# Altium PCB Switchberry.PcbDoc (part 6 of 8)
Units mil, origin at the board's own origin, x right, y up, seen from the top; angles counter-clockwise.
Board outline 4500 x 3824.8 mil, 6 copper layers (L01-TOP, L02-GND, L03-SIG, L04-SIG, L05-GND, L06-BOT), stack 49.214 mil thick; 431 components, 322 nets, 1699 pads, 1274 vias.
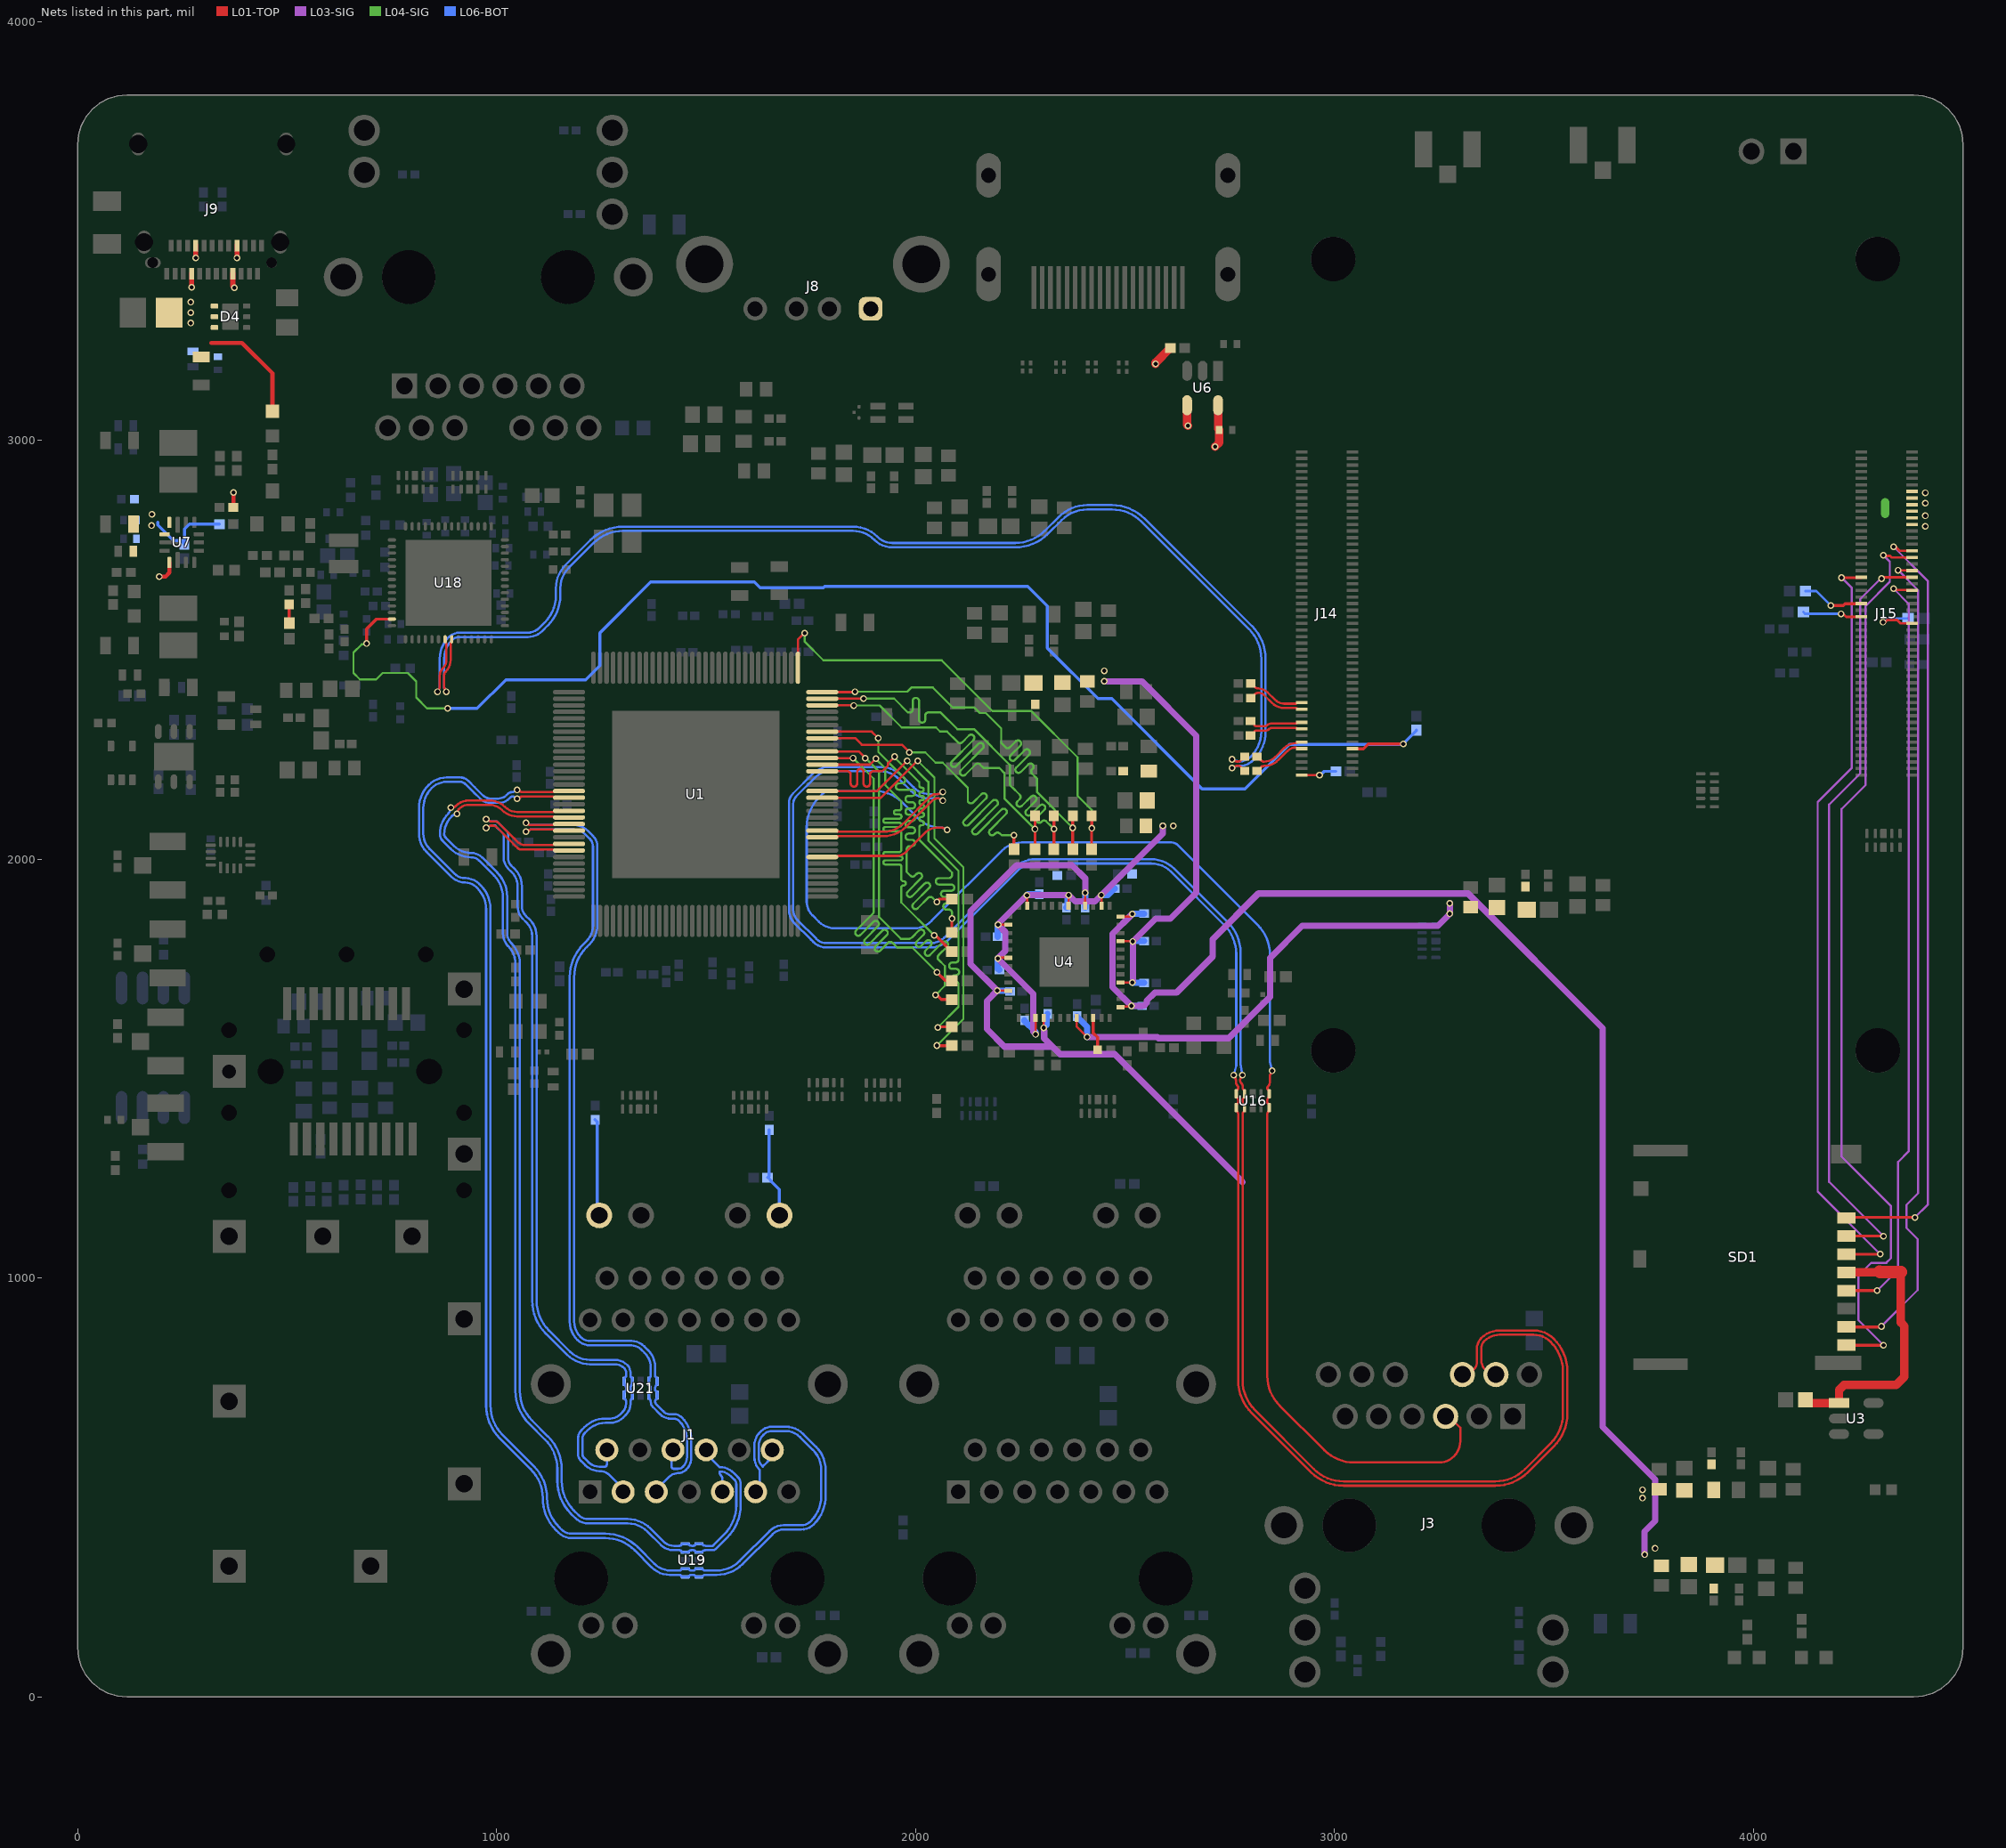
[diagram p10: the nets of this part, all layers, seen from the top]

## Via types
v1: diameter 16, hole 10, L01-TOP to L06-BOT, tented both sides, 1262 vias
v2: diameter 11.81, hole 7.87, L01-TOP to L06-BOT, tented both sides, 4 vias
v3: diameter 19.68, hole 7.87, L01-TOP to L06-BOT, tented both sides, 4 vias
v4: diameter 157.48, hole 110.24, L01-TOP to L06-BOT, tented both sides, 4 vias

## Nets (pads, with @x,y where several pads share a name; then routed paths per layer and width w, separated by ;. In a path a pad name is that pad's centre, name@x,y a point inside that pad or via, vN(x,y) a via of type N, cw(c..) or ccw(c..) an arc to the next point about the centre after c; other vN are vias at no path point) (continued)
P4_TXRXC_P: J3.3 U1.39 U16.1 U16.10 | length 3955.4
  L01-TOP w5.38: U1.39@1777.18,2005.39 1809.86,2005.39 ccw(c1809.86,2009.98) 1813.1,2006.74 cw(c1816.34,2003.5) 1816.34,2008.08 1954.23,2008.08 ccw(c1954.23,2040.73) 1977.32,2017.64 2025.21,2065.54 cw(c2048.75,2042.08) 2048.75,2075.31 2063.06,2075.31 cw(c2063.06,2066.24) 2069.47,2072.66 2070.09,2072.03 ccw(c2075,2076.94) v1(2075,2070) ; v1(2851,1495) cw(c2844.06,1495) 2848.97,1490.1 2848.34,1489.47 ccw(c2854.76,1483.06) 2845.69,1483.06 2845.69,1468.99 cw(c2829.6,1468.99) 2840.98,1457.61 ccw(c2844.78,1453.81) 2839.4,1453.81 ccw(c2844.78,1453.81) 2840.98,1450.01 2842.55,1448.43 2842.81,1448.43 2843.43,1447.81 cw(c2841.92,1446.3) 2844.06,1446.3 U16.1@2844.06,1440 2844.06,1433.7 cw(c2841.92,1433.7) 2843.43,1432.19 2842.81,1431.57 2842.55,1431.57 ccw(c2850.16,1423.96) 2839.4,1423.96 2839.4,1420.94 ccw(c2844.78,1420.94) 2840.98,1417.13 2842.55,1415.56 2842.81,1415.56 cw(c2839.79,1412.55) 2844.06,1412.55 U16.10@2844.06,1407.13 2844.06,1400.82 cw(c2841.92,1400.82) 2843.43,1399.32 2842.81,1398.69 2842.55,1398.69 ccw(c2850.16,1391.09) 2839.4,1391.09 2839.4,767.02 ccw(c2939.4,767.02) 2868.69,696.31 2975.71,589.29 ccw(c3046.42,660) 3046.42,560 3248.79,560 ccw(c3248.79,611.21) 3285,575 ccw(c3249.13,610.87) 3299.86,610.87 3299.86,643.32 3278.96,664.22 ccw(c3265,650.25) J3.3@3265,670
  L06-BOT w5.38: 1903.45,2162.87 1792.39,2162.87 ccw(c1792.39,2144.56) 1779.44,2157.51 1769.29,2147.36 ccw(c1840,2076.65) 1740,2076.65 1740,1899.37 ccw(c1786.76,1899.37) 1753.69,1866.31 1769.16,1850.84 ccw(c1806.49,1888.17) 1806.49,1835.38 1996.42,1835.38 ccw(c1996.42,1894.01) 2037.87,1852.55 2205.98,2020.66 cw(c2253.55,1973.14) 2206.03,2020.71 cw(c2253.55,1973.14) 2253.55,2040.38 2604.05,2040.38 cw(c2604.05,1968.14) 2616.38,2039.32 cw(c2613.58,2023.81) 2624.71,2034.96 2644.51,2015.17 2816.4,1843.28 cw(c2745.69,1772.57) 2845.69,1772.57 2845.69,1519.71 2845.69,1516.94 v1(2851,1495) ; 1903.49,2162.87 cw(c1903.52,2072.77) 1967.25,2136.47 ; 1967.28,2136.43 2004.59,2099.13 ccw(c2062.09,2156.64) 2062.09,2075.31 2062.18,2075.31 cw(c2062.18,2064.12) 2070.09,2072.03 ccw(c2075,2076.94) v1(2075,2070)
P4_TXRXD_N: J3.9 U1.43 U16.5 U16.6 | length 4808.8
  L01-TOP w5.38: U1.43@1777.18,2068.39 1809.86,2068.39 cw(c1809.86,2063.8) 1813.1,2067.04 ccw(c1816.34,2070.28) 1816.34,2065.7 1923.41,2065.7 ccw(c1923.41,2131.59) 1970,2085 2034.99,2149.99 cw(c2048.75,2136.22) 2048.75,2155.69 2053.06,2155.69 ccw(c2053.06,2164.76) 2059.47,2158.34 2060.09,2158.97 cw(c2065,2154.06) v1(2065,2161) ; v1(2759,1485) ccw(c2765.94,1485) 2761.03,1480.1 2761.66,1479.47 cw(c2755.24,1473.06) 2764.31,1473.06 2764.31,1468.11 ccw(c2774.66,1468.11) 2767.34,1460.79 2767.64,1460.49 cw(c2762.02,1454.88) 2769.97,1454.88 cw(c2762.02,1454.88) 2767.64,1449.26 2766.82,1448.43 2766.56,1448.43 2765.94,1447.81 ccw(c2767.45,1446.3) 2765.31,1446.3 U16.5@2765.31,1440 2765.31,1433.7 ccw(c2767.45,1433.7) 2765.94,1432.19 2766.56,1431.57 2766.82,1431.57 cw(c2759.21,1423.96) 2769.97,1423.96 2769.97,1420.94 cw(c2764.59,1420.94) 2768.39,1417.13 2766.82,1415.56 2766.56,1415.56 ccw(c2769.58,1412.55) 2765.31,1412.55 U16.6@2765.31,1407.13 2765.31,1400.82 ccw(c2767.45,1400.82) 2765.94,1399.32 2766.56,1398.69 2766.82,1398.69 cw(c2759.21,1391.09) 2769.97,1391.09 2769.97,756.07 ccw(c2880.35,756.07) 2802.3,678.03 2943.37,536.95 ccw(c3021.42,615) 3021.42,504.62 3383.58,504.62 ccw(c3383.58,615) 3461.63,536.95 3523.05,598.37 ccw(c3445,676.42) 3555.38,676.42 3555.38,777.31 ccw(c3445,777.31) 3523.05,855.36 ccw(c3474.72,807.03) 3474.72,875.38 3393.8,875.38 ccw(c3393.8,813.79) 3350.25,857.34 ccw(c3375.9,831.69) 3339.62,831.69 3339.62,800.7 3339.81,800.51 cw(c3314.83,800.51) 3332.5,782.85 3330,780.35 cw(c3305,805.35) J3.9@3305,770
  L06-BOT w5.38: 1787.33,1789.62 cw(c1787.33,1834.49) 1755.62,1802.74 cw(c1787.33,1834.49) 1755.57,1802.79 1750.37,1807.99 1710.52,1847.84 cw(c1741.46,1878.84) 1710.46,1847.9 cw(c1741.46,1878.84) 1697.66,1878.84 1697.66,2133.22 cw(c1731.74,2133.22) 1707.64,2157.32 1754.05,2203.72 cw(c1794.61,2163.16) 1794.61,2220.53 1915.04,2220.53 cw(c1915.04,2145.1) 1968.34,2198.47 1994.98,2171.82 ccw(c2033.96,2210.86) 2033.96,2155.69 2053.06,2155.69 ccw(c2053.06,2164.76) 2059.47,2158.34 2060.09,2158.97 cw(c2065,2154.06) v1(2065,2161) ; 1787.36,1789.62 1796.49,1789.62 2037.23,1789.62 ccw(c2037.23,1843.68) 2075.44,1805.44 ; 2075.47,1805.47 2241.33,1971.33 ; 2241.35,1971.35 cw(c2286.4,1926.27) 2286.4,1990 2561.72,1990 cw(c2561.72,1921.72) 2610,1970 2736.02,1843.98 cw(c2665.31,1773.27) 2765.31,1773.27 2765.31,1507.49 v1(2759,1485)
P4_TXRXD_P: J3.8 U1.42 U16.4 U16.7 | length 4726.6
  L01-TOP w5.38: U1.42@1777.18,2052.64 1809.86,2052.64 ccw(c1809.86,2057.22) 1813.1,2053.98 cw(c1816.34,2050.74) 1816.34,2055.32 1923.51,2055.32 ccw(c1923.51,2131.34) 1977.26,2077.59 2040.81,2141.13 cw(c2050.9,2131.03) 2050.9,2145.31 2053.06,2145.31 cw(c2053.06,2136.24) 2059.47,2142.66 2060.09,2142.03 ccw(c2065,2146.94) v1(2065,2140) ; v1(2780,1485) cw(c2773.06,1485) 2777.97,1480.1 2777.34,1479.47 ccw(c2783.76,1473.06) 2774.69,1473.06 2774.69,1472.12 ccw(c2784.35,1472.12) 2777.52,1465.29 cw(c2770.69,1458.47) 2780.35,1458.47 2780.35,1456.04 ccw(c2791.1,1456.04) 2783.5,1448.43 2783.75,1448.43 2784.38,1447.81 cw(c2782.87,1446.3) 2785,1446.3 U16.4@2785,1440 2785,1433.7 cw(c2782.87,1433.7) 2784.38,1432.19 2783.75,1431.57 2783.5,1431.57 ccw(c2791.1,1423.96) 2780.35,1423.96 2780.35,1420.94 ccw(c2785.72,1420.94) 2781.92,1417.13 2783.5,1415.56 2783.75,1415.56 cw(c2780.74,1412.55) 2785,1412.55 U16.7@2785,1407.13 2785,1400.82 cw(c2782.87,1400.82) 2784.38,1399.32 2783.75,1398.69 2783.5,1398.69 ccw(c2791.1,1391.09) 2780.35,1391.09 2780.35,756.07 ccw(c2880.35,756.07) 2809.64,685.36 2950.71,544.29 ccw(c3021.42,615) 3021.42,515 3383.58,515 ccw(c3383.58,615) 3454.29,544.29 3515.71,605.71 ccw(c3445,676.42) 3545,676.42 3545,777.31 ccw(c3445,777.31) 3515.71,848.02 ccw(c3474.72,807.03) 3474.72,865 3393.8,865 ccw(c3393.8,813.79) 3357.58,850 ccw(c3375.9,831.69) 3350,831.69 3350,805 3350.19,804.81 3350.19,804.43 ccw(c3384.62,804.43) 3360.27,780.08 ccw(c3384.62,804.43) 3384.62,770 J3.8@3385,770
  L06-BOT w5.38: 1762.94,1810.1 1717.83,1855.21 cw(c1741.46,1878.84) 1708.04,1878.84 1708.04,2133.2 cw(c1731.8,2133.2) 1715,2150 1761.32,2196.32 cw(c1794.7,2162.95) 1794.7,2210.15 1914.99,2210.15 cw(c1914.99,2144.99) 1961.06,2191.07 1989.14,2162.99 ccw(c2031.81,2205.67) 2031.81,2145.31 2053.06,2145.31 cw(c2053.06,2136.24) 2059.47,2142.66 2060.09,2142.03 ccw(c2065,2146.94) v1(2065,2140) ; 1762.95,1810.08 ccw(c1787.33,1834.49) 1787.33,1800 2037.23,1800 ccw(c2037.23,1843.68) 2068.12,1812.79 2233.97,1978.64 cw(c2286.4,1926.27) 2234.02,1978.7 cw(c2286.4,1926.27) 2286.4,2000.38 2561.72,2000.38 cw(c2561.72,1921.72) 2617.36,1977.32 2623.59,1971.09 2746.4,1848.28 cw(c2675.69,1777.57) 2775.69,1777.57 2775.69,1514.7 2775.69,1511.94 v1(2780,1485)
P5_LED0: J1.31 R39.2 | length 232.4
  L06-BOT w7.27: R39.2@1235,1378.27 1240,1373.27 1240,1155 J1.31@1245,1150
P5_LED1: J1.34 R40.2 R103.1 | length 217.9
  L06-BOT w7.27: R40.2@1650.47,1354.06 1650.47,1243.74 R103.1@1646.73,1240 1647.72,1240 1655.89,1231.82 1655.89,1230.84 1675,1211.73 J1.34@1675,1150
P5_TXRXA_N: J1.13 U1.113 U19.2 U19.9 | length 3418.2
  L01-TOP w5.38: v1(1049.1,2144.5) ccw(c1049.1,2151.44) 1054,2146.53 1054.63,2147.16 cw(c1061.04,2140.74) 1061.04,2149.81 1133.66,2149.81 cw(c1133.66,2145.23) 1136.9,2148.47 ccw(c1140.14,2151.71) 1140.14,2147.13 U1.113@1172.82,2147.13
  L06-BOT w5.38: 840,2025 899.39,1965.61 ccw(c925,1991.21) 925,1955 925.09,1955 cw(c925.09,1907.71) 958.53,1941.15 962.34,1937.34 cw(c906.72,1881.72) 985.38,1881.72 985.38,696.12 ccw(c1085.38,696.12) 1014.67,625.41 1088.77,551.31 cw(c1012.47,475) 1120.38,475 ccw(c1217.86,475) 1148.93,406.07 1155,400 ccw(c1179.14,424.14) 1179.14,390 1258.96,390 cw(c1258.96,279.62) 1337.01,357.67 1376.45,318.23 ccw(c1415.53,357.3) 1415.53,302.04 1436.19,302.04 ccw(c1436.19,307.42) 1439.99,303.61 1441.57,305.19 1441.57,305.44 cw(c1444.58,302.43) 1444.58,306.69 U19.2@1450,306.69 1456.3,306.69 cw(c1456.3,304.56) 1457.81,306.07 1458.43,305.44 1458.43,305.19 ccw(c1466.04,312.8) 1466.04,302.04 1469.06,302.04 ccw(c1469.06,307.42) 1472.87,303.61 1474.44,305.19 1474.44,305.44 cw(c1477.45,302.43) 1477.45,306.69 U19.9@1482.87,306.69 1489.18,306.69 cw(c1489.18,304.56) 1490.68,306.07 1491.31,305.44 1491.31,305.19 ccw(c1498.91,312.8) 1498.91,302.04 1525,302.04 ccw(c1525,379.39) 1579.69,324.69 1651.5,396.5 cw(c1685,363.01) 1685,410.38 1726.77,410.38 ccw(c1726.77,443.23) 1750,420 ccw(c1689.64,480.36) 1775,480.36 1775,541.72 ccw(c1706.72,541.72) 1755,590 1724.14,620.86 ccw(c1690,586.72) 1690,635 1657.07,635 ccw(c1657.07,608.13) 1638.76,627.79 1636.71,625.89 ccw(c1660.61,600.22) 1625.54,600.22 1625.54,600.05 1625.54,572.84 ccw(c1657.84,572.84) 1635,550 1645.98,560.98 ccw(c1616.96,590) J1.13@1658,590 cw(c1625.79,590) J1.13@1648.57,567.22 ; 839.99,2025.01 cw(c876.21,2061.21) 825,2061.21 825,2121.72 cw(c893.28,2121.72) 845,2170 cw(c881.21,2133.79) 881.21,2185 912.93,2185 cw(c912.93,2167.93) 924.98,2180.02 947.34,2157.66 947.66,2157.66 960.63,2144.69 ccw(c984.94,2169) 984.94,2134.62 1004.16,2134.62 ccw(c1004.16,2172.02) 1030.6,2145.58 1032.69,2147.66 ; 1032.69,2147.67 cw(c1037.88,2142.47) 1037.88,2149.81 cw(c1037.88,2142.47) 1043.07,2147.66 1044.2,2146.53 ccw(c1049.1,2151.44) v1(1049.1,2144.5)
P5_TXRXA_P: J1.6 U1.112 U19.1 U19.10 | length 3509.5
  L01-TOP w5.38: v1(1049.1,2165.5) cw(c1049.1,2158.56) 1054,2163.47 1054.63,2162.84 ccw(c1061.04,2169.26) 1061.04,2160.19 1133.66,2160.19 ccw(c1133.66,2164.77) 1136.9,2161.53 cw(c1140.14,2158.29) 1140.14,2162.87 U1.112@1172.82,2162.87
  L06-BOT w5.38: 924.97,1944.62 cw(c924.97,1991.15) 892.07,1958.25 832.62,2017.71 cw(c876.06,2061.15) 814.62,2061.15 814.62,2121.82 cw(c893.04,2121.82) 837.59,2177.27 837.68,2177.36 cw(c881.19,2133.85) 881.19,2195.38 912.93,2195.38 cw(c912.93,2167.93) 932.34,2187.34 947.5,2172.18 947.82,2172.18 967.93,2152.07 ccw(c985,2169.14) 985,2145 1004.13,2145 ccw(c1004.13,2172.08) 1023.28,2152.93 1026.48,2156.13 cw(c1036.28,2146.32) 1036.28,2160.19 ccw(c1036.28,2171.38) 1044.2,2163.47 cw(c1049.1,2158.56) v1(1049.1,2165.5) ; 925,1944.62 cw(c925,1907.5) 951.25,1933.75 953.79,1931.21 cw(c902.57,1880) 975,1880 975,696.09 ccw(c1085.31,696.09) 1007.31,618.09 1081.43,543.97 cw(c1012.47,475) 1110,475 ccw(c1217.86,475) 1141.59,398.73 1147.66,392.66 ccw(c1179.14,424.14) 1179.14,379.62 1258.96,379.62 cw(c1258.96,279.62) 1329.67,350.33 1370.63,309.37 ccw(c1413.38,352.11) 1413.38,291.66 1436.19,291.66 cw(c1436.19,286.28) 1439.99,290.09 1441.57,288.51 1441.57,288.26 ccw(c1444.58,291.27) 1444.58,287.01 U19.1@1450,287.01 1456.3,287.01 ccw(c1456.3,289.14) 1457.81,287.63 1458.43,288.26 1458.43,288.51 cw(c1466.04,280.91) 1466.04,291.66 1469.06,291.66 cw(c1469.06,286.28) 1472.87,290.09 1474.44,288.51 1474.44,288.26 ccw(c1477.45,291.27) 1477.45,287.01 U19.10@1482.87,287.01 1489.18,287.01 ccw(c1489.18,289.14) 1490.68,287.63 1491.31,288.26 1491.31,288.51 cw(c1498.91,280.91) 1498.91,291.66 1525,291.66 ccw(c1525,379.39) 1587.03,317.36 1658.84,389.16 cw(c1685,363.01) 1685,400 1726.77,400 ccw(c1726.77,443.23) 1757.34,412.66 ccw(c1689.64,480.36) 1785.38,480.36 1785.38,541.72 ccw(c1706.72,541.72) 1762.34,597.34 1731.48,628.2 ccw(c1690,586.72) 1690,645.38 1657.07,645.38 ccw(c1657.07,608.13) 1631.69,635.39 1629.64,633.48 ccw(c1660.61,600.22) 1615.16,600.22 1615.16,600.04 1615.16,572.84 ccw(c1657.84,572.84) 1627.66,542.66 1627.66,513.33 cw(c1594.67,513.33) J1.6@1618,490 ccw(c1600.53,507.47) J1.6@1625.24,507.47
P5_TXRXB_N: J1.5 U1.116 U19.5 U19.6 | length 2725.1
  L01-TOP w5.38: v1(905.72,2108.21) 905.72,2109.66 cw(c920.34,2109.66) 910,2120 cw(c934.14,2095.86) 934.14,2130 982.87,2130 cw(c982.87,2087.87) 1012.66,2117.66 1012.72,2117.6 ccw(c1049.02,2153.9) 1049.02,2102.57 1133.66,2102.57 cw(c1133.66,2097.98) 1136.9,2101.22 ccw(c1140.14,2104.47) 1140.14,2099.88 U1.116@1172.82,2099.88
  L06-BOT w5.38: v1(905.72,2108.21) cw(c900.81,2113.11) 900.81,2106.17 ccw(c900.81,2094.98) 892.9,2102.9 ccw(c936.1,2059.69) 875,2059.69 ccw(c886.33,2059.69) 878.32,2051.68 897.32,2032.68 ccw(c940,2075.36) 940,2015 cw(c940.03,1979.63) 965.04,2004.64 1001.2,1968.47 cw(c942.84,1910.11) 1025.38,1910.11 1025.38,1823.23 ccw(c1058.23,1823.23) 1035,1800 cw(c985.92,1750.85) 1055.38,1750.85 1055.38,731.04 ccw(c1155.38,731.04) 1084.67,660.33 1123.05,621.95 cw(c1045,543.9) 1155.38,543.9 1155.38,516.04 ccw(c1255.38,516.04) 1184.67,445.33 1195,435 ccw(c1219.14,459.14) 1219.14,425 1312.63,425 cw(c1312.63,347.63) 1367.34,402.34 1398.03,371.64 ccw(c1423.5,397.11) 1423.5,361.09 1436.19,361.09 ccw(c1436.19,366.47) 1439.99,362.67 1441.57,364.24 1441.57,364.5 cw(c1444.58,361.49) 1444.58,365.75 U19.5@1450,365.75 1456.3,365.75 cw(c1456.3,363.62) 1457.81,365.12 1458.43,364.5 1458.43,364.24 ccw(c1466.04,371.85) 1466.04,361.09 1469.06,361.09 ccw(c1469.06,366.47) 1472.87,362.67 1474.44,364.24 1474.44,364.5 cw(c1477.45,361.49) 1477.45,365.75 U19.6@1482.87,365.75 1489.18,365.75 cw(c1489.18,363.62) 1490.68,365.12 1491.31,364.5 1491.31,364.24 ccw(c1498.91,371.85) 1498.91,361.09 1515,361.09 ccw(c1515,363.74) 1516.87,361.87 1542.81,387.81 ccw(c1472.1,458.52) 1572.1,458.52 1572.1,508.52 ccw(c1558.04,508.52) 1567.98,518.46 1559.22,527.23 ccw(c1532.11,500.12) 1532.11,538.45 1532.11,537.17 ccw(c1543.87,537.17) 1535.56,528.85 cw(c1527.24,520.54) 1539,520.54 J1.5@1539,490
P5_TXRXB_P: J1.11 U1.115 U19.4 U19.7 | length 2793.7
  L01-TOP w5.38: v1(890.87,2123.06) 892.32,2123.06 ccw(c892.32,2137.68) 902.66,2127.34 902.73,2127.4 cw(c934.05,2096.08) 934.05,2140.38 983,2140.38 cw(c983,2088.19) 1019.91,2125.09 1020,2125 ccw(c1049.1,2154.1) 1049.1,2112.94 1133.66,2112.94 ccw(c1133.66,2117.53) 1136.9,2114.29 cw(c1140.14,2111.05) 1140.14,2115.63 U1.115@1172.82,2115.63
  L06-BOT w5.38: 885.52,2110.2 ccw(c935.99,2059.74) 864.62,2059.74 864.62,2059.65 ccw(c886.21,2059.65) 870.95,2044.38 890.03,2025.3 ccw(c939.94,2075.21) 939.94,2004.62 940,2004.62 cw(c940,1979.57) 957.72,1997.28 993.79,1961.21 cw(c942.57,1910) 1015,1910 1015,1823.19 ccw(c1058.14,1823.19) 1027.64,1792.69 ; 885.56,2110.23 ccw(c877.64,2118.15) 888.84,2118.15 cw(c895.77,2118.15) v1(890.87,2123.06) ; 1027.66,1792.66 cw(c985.8,1750.8) 1045,1750.8 1045,731.02 ccw(c1155.31,731.02) 1077.31,653.01 1115.71,614.61 cw(c1045,543.9) 1145,543.9 1145,516.04 ccw(c1255.38,516.04) 1177.33,437.99 1187.66,427.66 ccw(c1219.14,459.14) 1219.14,414.62 1312.63,414.62 cw(c1312.63,347.63) 1360,395 1392.22,362.78 ccw(c1421.35,391.92) 1421.35,350.72 1436.19,350.72 cw(c1436.19,345.34) 1439.99,349.14 1441.57,347.57 1441.57,347.31 ccw(c1444.58,350.32) 1444.58,346.06 U19.4@1450,346.06 1456.3,346.06 ccw(c1456.3,348.19) 1457.81,346.69 1458.43,347.31 1458.43,347.57 cw(c1466.04,339.96) 1466.04,350.72 1469.06,350.72 cw(c1469.06,345.34) 1472.87,349.14 1474.44,347.57 1474.44,347.31 ccw(c1477.45,350.32) 1477.45,346.06 U19.7@1482.87,346.06 1489.18,346.06 ccw(c1489.18,348.19) 1490.68,346.69 1491.31,347.31 1491.31,347.57 cw(c1498.91,339.96) 1498.91,350.72 1515,350.72 ccw(c1515,363.74) 1524.21,354.53 1550.15,380.47 ccw(c1472.1,458.52) 1582.48,458.52 1582.48,508.52 ccw(c1558.04,508.52) 1575.32,525.8 1566.55,534.57 ccw(c1532.11,500.12) 1532.11,548.83 1506.4,574.54 cw(c1521.86,590) J1.11@1500,590
P5_TXRXC_N: J1.10 U1.118 U21.2 U21.9 | length 2059.6
  L01-TOP w5.38: v1(1070,2065.76) ccw(c1070,2072.7) 1074.9,2067.79 1075.53,2068.42 cw(c1081.94,2062) 1081.94,2071.07 1133.66,2071.07 cw(c1133.66,2066.49) 1136.9,2069.73 ccw(c1140.14,2072.97) 1140.14,2068.39 U1.118@1172.82,2068.39
  L06-BOT w5.38: v1(1070,2065.76) ccw(c1070,2072.7) 1074.91,2067.79 cw(c1082.82,2059.88) 1082.82,2071.07 1185,2071.07 cw(c1185,2034.86) 1210.57,2060.5 cw(c1185,2034.86) 1210.61,2060.46 1211.29,2059.78 1222.58,2048.49 cw(c1204.59,2030.55) 1230,2030.55 1230,1843.1 cw(c1174.25,1843.1) 1213.76,1803.77 cw(c1150.05,1867.27) 1213.71,1803.72 1206.92,1796.92 ccw(c1284.89,1718.95) 1174.62,1718.95 1174.62,896.21 ccw(c1236.21,896.21) 1192.66,852.66 ccw(c1224.14,884.14) 1224.14,839.62 1321.77,839.62 cw(c1321.77,806.77) 1345,830 1353.2,821.8 cw(c1317.58,786.17) 1367.96,786.17 1367.96,767.53 cw(c1362.58,767.53) 1366.39,763.73 1364.81,762.15 1364.55,762.15 ccw(c1367.57,759.14) 1363.31,759.14 U21.9@1363.31,753.72 1363.31,747.42 ccw(c1365.44,747.42) 1363.93,745.91 1364.55,745.29 1364.81,745.29 cw(c1357.2,737.68) 1367.96,737.68 1367.96,734.66 cw(c1362.58,734.66) 1366.39,730.85 1364.81,729.28 1364.55,729.28 ccw(c1367.57,726.27) 1363.31,726.27 U21.2@1363.31,720.85 1363.31,714.54 ccw(c1365.44,714.54) 1363.93,713.04 1364.55,712.41 1364.81,712.41 cw(c1357.2,704.81) 1367.96,704.81 ccw(c1385.93,704.81) 1373.22,692.1 1390.59,674.73 ccw(c1415,699.14) 1415,664.62 1423.84,664.62 cw(c1423.84,648.84) 1435,660 cw(c1388.18,613.18) 1454.39,613.18 1454.39,572.67 cw(c1422.33,572.67) 1445,550 cw(c1432.93,562.07) 1432.93,545 1422.98,545 cw(c1422.98,550.38) 1419.18,546.58 cw(c1422.98,550.38) 1417.61,550.38 1417.61,581.81 cw(c1429.19,581.81) J1.10@1421,590
P5_TXRXC_P: J1.3 U1.117 U21.1 U21.10 | length 2105
  L01-TOP w5.38: v1(1070,2086.76) cw(c1070,2079.82) 1074.9,2084.73 1075.53,2084.1 ccw(c1081.94,2090.52) 1081.94,2081.45 1133.66,2081.45 ccw(c1133.66,2086.03) 1136.9,2082.79 cw(c1140.14,2079.55) 1140.14,2084.13 U1.117@1172.82,2084.13
  L06-BOT w5.38: v1(1070,2086.76) cw(c1070,2079.82) 1074.91,2084.73 ccw(c1082.82,2092.64) 1082.82,2081.45 1185,2081.45 cw(c1185,2034.86) 1217.93,2067.82 ; 1217.94,2067.8 1229.9,2055.85 cw(c1204.59,2030.55) 1240.38,2030.55 1240.38,1843.1 cw(c1174.25,1843.1) 1221.01,1796.34 1214.29,1789.62 ccw(c1285,1718.91) 1185,1718.91 1185,896.21 ccw(c1236.21,896.21) 1200,860 ccw(c1224.14,884.14) 1224.14,850 1321.77,850 cw(c1321.77,806.77) 1352.34,837.34 1362.06,827.61 cw(c1322.77,788.32) 1378.34,788.32 1378.34,767.53 ccw(c1383.72,767.53) 1379.91,763.73 1381.49,762.15 1381.74,762.15 cw(c1378.73,759.14) 1382.99,759.14 U21.10@1382.99,753.72 1382.99,747.42 cw(c1380.86,747.42) 1382.37,745.91 1381.74,745.29 1381.49,745.29 ccw(c1389.09,737.68) 1378.34,737.68 1378.34,734.66 ccw(c1383.72,734.66) 1379.91,730.85 1381.49,729.28 1381.74,729.28 cw(c1378.73,726.27) 1382.99,726.27 U21.1@1382.99,720.85 1382.99,714.54 cw(c1380.86,714.54) 1382.37,713.04 1381.74,712.41 1381.49,712.41 1381.03,711.95 ccw(c1387.51,705.46) 1378.34,705.46 ccw(c1387.51,705.46) 1381.03,698.97 1397.93,682.07 ccw(c1415,699.14) 1415,675 1423.84,675 cw(c1423.84,648.84) 1442.34,667.34 cw(c1388.18,613.18) 1464.77,613.18 1464.77,572.67 cw(c1422.33,572.67) 1452.34,542.66 cw(c1432.93,562.07) 1432.93,534.62 ccw(c1432.93,505.23) 1412.15,526.01 1384.44,498.31 ccw(c1392.75,490) J1.3@1381,490
P5_TXRXD_N: J1.2 U1.121 U21.5 U21.6 | length 2146.8
  L01-TOP w5.38: v1(975,2075) ccw(c975,2081.94) 979.9,2077.03 980.53,2077.66 cw(c986.94,2071.24) 986.94,2080.31 991.77,2080.31 cw(c991.77,2068.65) 1000.01,2076.9 1031.72,2045.19 ; 1031.78,2045.13 1043.95,2032.96 1050.01,2026.9 ; 1050.05,2026.86 ccw(c1057.38,2034.2) 1057.38,2023.83 1078.91,2023.83 1133.66,2023.83 cw(c1133.66,2019.24) 1136.9,2022.48 ccw(c1140.14,2025.73) 1140.14,2021.14 U1.121@1172.82,2021.14
  L06-BOT w5.38: v1(975,2075) ccw(c975,2081.94) 979.91,2077.03 cw(c987.82,2069.12) 987.82,2080.31 996.44,2080.31 1017,2059.75 1017,2044.1 1016.96,2044.07 1016.96,2003.45 ccw(c1053.38,2003.45) 1027.63,1977.69 1035.63,1969.69 cw(c1000.94,1935) 1050,1935 1050,1888.16 ccw(c1093.07,1888.16) 1062.62,1857.71 1071.77,1848.55 cw(c1039.84,1816.62) 1085,1816.62 1085,946.04 ccw(c1195.38,946.04) 1117.33,867.99 1158.37,826.95 1167.67,817.65 ccw(c1223.28,873.28) 1223.28,794.62 1281.77,794.62 cw(c1281.77,761.77) 1305,785 cw(c1295.57,775.57) 1308.91,775.57 1308.91,767.53 cw(c1303.53,767.53) 1307.33,763.73 1305.76,762.15 1305.5,762.15 ccw(c1308.51,759.14) 1304.25,759.14 U21.6@1304.25,753.72 1304.25,747.42 ccw(c1306.38,747.42) 1304.88,745.91 1305.5,745.29 1305.76,745.29 cw(c1298.15,737.68) 1308.91,737.68 1308.91,734.66 cw(c1303.53,734.66) 1307.33,730.85 1305.76,729.28 1305.5,729.28 ccw(c1308.51,726.27) 1304.25,726.27 U21.5@1304.25,720.85 1304.25,714.54 ccw(c1306.38,714.54) 1304.88,713.04 1305.5,712.41 1305.76,712.41 cw(c1298.15,704.81) 1308.91,704.81 1308.91,700 cw(c1282.12,700) 1301.06,681.06 1295,675 cw(c1270.86,699.14) 1270.86,665 1260,665 ccw(c1260,593.35) 1209.34,644.02 1202.66,637.34 ccw(c1222.07,617.93) 1194.62,617.93 1194.62,580 ccw(c1217.07,580) 1201.2,564.13 1211.93,553.39 ccw(c1245.18,586.64) 1245.18,539.62 cw(c1245.18,504.2) 1270.22,529.25 1296.72,502.76 cw(c1283.96,490) J1.2@1302,490
P5_TXRXD_P: J1.8 U1.120 U21.4 U21.7 | length 2122.4
  L01-TOP w5.38: v1(975,2096) cw(c975,2089.06) 979.9,2093.97 980.53,2093.34 ccw(c986.94,2099.76) 986.94,2090.69 996.6,2090.69 cw(c996.6,2080.31) 1003.93,2087.66 ; 1003.95,2087.64 1042.1,2049.48 1042.16,2049.42 1049.77,2041.81 ccw(c1068.14,2060.19) 1068.14,2034.2 1078.99,2034.2 1133.66,2034.2 ccw(c1133.66,2038.79) 1136.9,2035.55 cw(c1140.14,2032.31) 1140.14,2036.89 U1.120@1172.82,2036.89
  L06-BOT w5.38: v1(975,2096) cw(c975,2089.06) 979.91,2093.97 ccw(c987.82,2101.88) 987.82,2090.69 996.48,2090.69 cw(c996.48,2080.41) 1003.75,2087.68 1024.34,2067.09 ; 1024.34,2067.09 cw(c1017,2059.75) 1027.38,2059.75 1027.38,2039.81 1027.34,2039.77 1027.34,2003.5 ccw(c1053.5,2003.5) 1035,1985 1043.06,1976.94 cw(c1001.24,1935.13) 1060.38,1935.13 1060.38,1888.23 ccw(c1093.23,1888.23) 1070,1865 1079.18,1855.82 cw(c1040.07,1816.71) 1095.38,1816.71 1095.38,946.04 ccw(c1195.38,946.04) 1124.67,875.33 1175,825 ccw(c1223.28,873.28) 1223.28,805 1281.77,805 cw(c1281.77,761.77) 1312.34,792.34 cw(c1295.57,775.57) 1319.28,775.57 1319.28,767.53 ccw(c1324.66,767.53) 1320.86,763.73 1322.43,762.15 1322.69,762.15 cw(c1319.68,759.14) 1323.94,759.14 U21.7@1323.94,753.72 1323.94,747.42 cw(c1321.81,747.42) 1323.31,745.91 1322.69,745.29 1322.43,745.29 ccw(c1330.04,737.68) 1319.28,737.68 1319.28,734.66 ccw(c1324.66,734.66) 1320.86,730.85 1322.43,729.28 1322.69,729.28 cw(c1319.68,726.27) 1323.94,726.27 U21.4@1323.94,720.85 1323.94,714.54 cw(c1321.81,714.54) 1323.31,713.04 1322.69,712.41 1322.43,712.41 ccw(c1330.04,704.81) 1319.28,704.81 1319.28,700 cw(c1282.12,700) 1308.4,673.72 1302.34,667.66 cw(c1270.86,699.14) 1270.86,654.62 1260,654.62 ccw(c1260,593.35) 1216.68,636.68 1210,630 ccw(c1222.07,617.93) 1205,617.93 1205,580 ccw(c1217.07,580) 1208.54,571.46 1219.27,560.73 ccw(c1245.18,586.64) 1245.18,550 1257.62,550 ccw(c1257.62,555.38) 1261.42,551.58 ccw(c1257.62,555.38) 1263,555.38 J1.8@1263,590
P5V: C34.2 C35.1 C36.1 C37.1 C38.1 C39.1 C40.2 C41.2 C42.1 C43.1 C44.1 C45.1 D4.4 D4.5 D4.6 D5.2 J8.1 J9.A4 J9.A9 J9.B4 J9.B9 J15.77 J15.79 J15.81 J15.83 J15.85 J15.87 R55.1 R56.2 R57.2 R62.2 U6.4 U6.5 U7.7 U7.8 U7.11 | length 928.3
  L01-TOP w10: v1(195,2675) 210,2675 219.1,2684.1 U7.11@219.1,2708.58 ; 319.15,3232.6 392.4,3232.6 465,3160 D5.2@465,3069.53 ; R62.2@371.73,2840 371.73,2874.89 v1(372.32,2875.48)
  L01-TOP w12: J9.A9@272.05,3398.07 272.05,3365.83 v1(272.2,3365.67) ; J9.B4@281.89,3465 281.97,3464.92 281.97,3435.78 v1(282.06,3435.7) ; J9.A4@370.47,3398.07 370.47,3368.32 v1(374.45,3364.34) ; v1(380.04,3435.7) 380.31,3435.97 J9.B9@380.31,3465
  L01-TOP w20: v1(2572.81,3182.49) 2572.81,3185.53 2607.28,3220 R55.1@2608.27,3220 ; U6.4@2648.01,3083.93 2648.01,3036.99 v1(2650,3035) ; v1(2715,2985) 2724.25,2994.25 C34.2@2724.25,3025 2721.99,3027.26 U6.5@2721.99,3083.93
  L04-SIG w20: 4314,2825 4314,2852
  L06-BOT w7.27: 191.54,2804.75 191.54,2797.66 228.31,2760.89 246.82,2760.89 R56.2@255,2752.72 ; R56.2@255,2751.73 R56.2@255,2752.72 ; R57.2@338.27,2800 266.49,2800 255,2788.51 R56.2@255,2752.72
  other v1: 4410,2795 176.36,2796.64 4410,2820 177.22,2823.74 4410,2850 4410,2875 270,3280 270,3305 270,3330
P6_LED0: R95.2
P6_LED1: R96.2
P6_RGMII_RXCLK: R14.1 U1.57 | length 1067.4
  L01-TOP w5.38: U1.57@1777.18,2288.86 1777.77,2289.44 1855.56,2289.44 1871.58,2273.42 1967.04,2273.42 v1(1985.09,2255.37)
  L01-TOP w7.27: v1(2234.81,2057.28) 2235,2057.08 R14.1@2235,2023.7
  L04-SIG w4.97: v1(1985.09,2255.37) 1985.47,2255 2023.1,2255 2047.61,2230.49 2064.51,2230.49 2124.51,2170.49 2124.51,2137.97 2125.04,2137.44 2126.8,2135.68 ccw(c2132.09,2140.97) 2137.39,2135.68 2157.11,2155.4 cw(c2162.4,2150.11) 2167.7,2155.4 cw(c2162.4,2150.11) 2167.7,2144.82 2115.98,2093.1 ccw(c2121.27,2087.8) 2115.98,2082.51 ccw(c2121.27,2087.8) 2126.56,2082.51 2183.77,2139.72 cw(c2189.06,2134.42) 2194.35,2139.72 cw(c2189.06,2134.42) 2194.35,2129.13 2137.15,2071.93 ccw(c2142.44,2066.63) 2137.15,2061.34 ccw(c2142.44,2066.63) 2147.73,2061.34 2204.94,2118.55 cw(c2210.23,2113.25) 2215.53,2118.55 cw(c2210.23,2113.25) 2215.53,2107.96 2177.44,2069.87 ccw(c2182.73,2064.58) 2177.44,2059.29 ccw(c2182.73,2064.58) 2188.02,2059.29 2190.32,2061.58 cw(c2195.61,2056.29) 2200.9,2061.58 2205.21,2057.28 2213.09,2057.28 v1(2234.81,2057.28)
P6_RGMII_RXCTL: R15.1 U1.58 | length 1053.3
  L01-TOP w5.38: U1.58@1777.18,2304.61 1895.43,2304.61 v1(1910.93,2289.11)
  L01-TOP w7.27: v1(2050.5,1898.06) 2057.43,1905 R15.1@2086.3,1905
  L04-SIG w4.97: v1(1910.93,2289.11) 1910.93,2255.97 1955.85,2211.05 1972.94,2193.96 cw(c1967.65,2188.66) 1967.65,2181.18 1960.13,2181.18 ccw(c1960.13,2173.69) 1960.13,2166.21 1991.36,2166.21 cw(c1991.36,2158.72) 1991.36,2151.24 1983.33,2151.24 ccw(c1983.33,2143.75) 1983.33,2136.26 1991.36,2136.26 cw(c1991.36,2128.78) 1991.36,2121.29 1983.33,2121.29 ccw(c1983.33,2113.81) 1983.33,2106.32 1991.36,2106.32 cw(c1991.36,2098.84) 1991.36,2091.35 1983.33,2091.35 ccw(c1983.33,2083.87) 1983.33,2076.38 1991.36,2076.38 cw(c1991.36,2068.89) 1991.36,2061.41 1983.33,2061.41 ccw(c1983.33,2053.92) 1983.33,2046.44 1991.36,2046.44 cw(c1991.36,2038.95) 1991.36,2031.47 1986.2,2031.47 ccw(c1986.2,2023.98) 1978.72,2023.98 1978.72,1976.58 1978.72,1974.1 1978.72,1969.84 1987.65,1960.91 ccw(c1992.94,1966.2) 1998.24,1960.91 2002.61,1965.28 cw(c2007.9,1959.99) 2013.19,1965.28 cw(c2007.9,1959.99) 2013.19,1954.7 1981.14,1922.64 ccw(c1986.43,1917.35) 1981.14,1912.06 ccw(c1986.43,1917.35) 1991.73,1912.06 2021.86,1942.19 cw(c2027.15,1936.9) 2032.44,1942.19 cw(c2027.15,1936.9) 2032.44,1931.6 1994.64,1893.8 ccw(c1999.93,1888.5) 1994.64,1883.21 ccw(c1999.93,1888.5) 2005.22,1883.21 2029.99,1907.98 cw(c2035.29,1902.69) 2040.58,1907.98 2042.34,1906.22 v1(2050.5,1898.06)
P6_RGMII_RXD0: R13.2 R16.1 U1.65 | length 1139
  L01-TOP w5.38: U1.65@1719.09,2457.18 1719.09,2524.09 v1(1735,2540)
  L01-TOP w7.27: R16.1@2420,2023.7 2420,2073.52 v1(2420.62,2074.13) 2420.62,2102.65 R13.2@2420,2103.27
  L04-SIG w4.97: v1(1735,2540) 1735,2520 1780,2475 2062.25,2475 2183.66,2353.58 2276.42,2353.58 2386.69,2243.31 2386.69,2151.76 2420.62,2117.82 v1(2420.62,2074.13)
P6_RGMII_RXD1: R12.2 R17.1 U1.64 | length 1067.2
  L01-TOP w5.38: U1.64@1777.18,2399.09 1854.09,2399.09 v1(1855,2400)
  L01-TOP w7.27: R17.1@2375,2023.7 v1(2375,2075) R12.2@2375,2103.27
  L04-SIG w4.97: v1(1855,2400) 1980,2400 1990,2410 2041.27,2410 2089.12,2362.15 2140.4,2362.15 2153.27,2349.28 2167.62,2349.28 2204.44,2312.46 2204.44,2277.67 2212.84,2269.27 2214.6,2267.51 ccw(c2219.9,2272.81) 2225.19,2267.51 2239.24,2281.56 cw(c2244.53,2276.27) 2249.82,2281.56 cw(c2244.53,2276.27) 2249.82,2270.98 2226.79,2247.95 ccw(c2232.09,2242.65) 2226.79,2237.36 ccw(c2232.09,2242.65) 2237.38,2237.36 2260.41,2260.39 cw(c2265.7,2255.1) 2271,2260.39 cw(c2265.7,2255.1) 2271,2249.8 2240.26,2219.07 ccw(c2245.56,2213.78) 2240.26,2208.49 ccw(c2245.56,2213.78) 2250.85,2208.49 2268.94,2226.58 cw(c2274.23,2221.28) 2279.53,2226.58 cw(c2274.23,2221.28) 2279.53,2215.99 2278.12,2214.58 ccw(c2283.41,2209.29) 2278.12,2204 2286.2,2195.92 2290.08,2192.03 2290.08,2159.92 v1(2375,2075)
P6_RGMII_RXD2: R11.2 R18.1 U1.63 | length 1067.2
  L01-TOP w5.38: U1.63@1777.18,2383.35 1777.33,2383.49 1875.74,2383.49 v1(1875.88,2383.63)
  L01-TOP w7.27: R18.1@2330,2023.7 v1(2330,2072.26) R11.2@2330,2103.27
  L04-SIG w4.97: v1(1875.88,2383.63) 1948.74,2383.63 1981.89,2350.49 1983.14,2350.49 1985.62,2350.49 ccw(c1985.62,2357.97) 1993.11,2357.97 1993.11,2377.94 cw(c2000.59,2377.94) 2008.08,2377.94 2008.08,2333.55 ccw(c2015.56,2333.55) 2023.05,2333.55 2023.05,2343 cw(c2030.53,2343) 2030.53,2350.49 2059.89,2350.49 2099.78,2310.59 2139.46,2310.59 2225,2225.05 2225,2177.26 2235.92,2166.34 2237.68,2164.58 2248.27,2153.99 cw(c2242.97,2148.7) 2248.27,2143.41 2243.22,2138.36 ccw(c2248.51,2133.06) 2243.22,2127.77 ccw(c2248.51,2133.06) 2253.8,2127.77 2275.67,2149.64 cw(c2280.97,2144.35) 2286.26,2149.64 cw(c2280.97,2144.35) 2286.26,2139.05 2264.39,2117.19 ccw(c2269.68,2111.89) 2264.39,2106.6 ccw(c2269.68,2111.89) 2274.97,2106.6 2296.84,2128.47 cw(c2302.14,2123.18) 2307.43,2128.47 cw(c2302.14,2123.18) 2307.43,2117.88 2289.46,2099.91 ccw(c2294.75,2094.62) 2289.46,2089.33 ccw(c2294.75,2094.62) 2300.05,2089.33 2301.2,2090.48 cw(c2306.49,2085.18) 2311.78,2090.48 2318.25,2084.02 2320,2082.26 v1(2330,2072.26)
P6_RGMII_RXD3: R10.2 R19.1 U1.62 | length 1067.2
  L01-TOP w5.38: U1.62@1777.18,2367.6 1852.04,2367.6 v1(1852.55,2367.09)
  L01-TOP w7.27: R19.1@2285,2023.7 v1(2285,2071.89) R10.2@2285,2103.27
  L04-SIG w4.97: v1(1852.55,2367.09) 1914.4,2367.09 1966.75,2314.73 2048.6,2314.73 2058.33,2305 2075,2305 2098.94,2281.06 2100.7,2279.3 ccw(c2105.99,2284.59) 2111.29,2279.3 2127.32,2295.33 cw(c2132.61,2290.04) 2137.9,2295.33 cw(c2132.61,2290.04) 2137.9,2284.74 2086.42,2233.26 ccw(c2091.72,2227.97) 2086.42,2222.68 ccw(c2091.72,2227.97) 2097.01,2222.68 2149.85,2275.52 cw(c2155.14,2270.22) 2160.43,2275.52 cw(c2155.14,2270.22) 2160.43,2264.93 2108.04,2212.53 ccw(c2113.33,2207.24) 2108.04,2201.95 ccw(c2113.33,2207.24) 2118.62,2201.95 2143.04,2226.37 cw(c2148.34,2221.08) 2153.63,2226.37 2161.79,2218.21 2196.48,2218.21 2199.66,2218.21 2211.94,2205.93 2211.94,2144.95 v1(2285,2071.89)
P6_RGMII_TXCLK: R20.1 U1.48 | length 1050.8
  L01-TOP w5.38: U1.48@1777.18,2147.13 1917.13,2147.13 v1(2005,2235)
  L01-TOP w7.27: v1(2050.72,1555.44) 2051.16,1555 R20.1@2086.3,1555
  L04-SIG w4.97: v1(2005,2235) 2045,2195 2045,2050.04 2113.93,1981.11 2113.93,1618.65 v1(2050.72,1555.44)
P6_RGMII_TXCTL: R21.1 U1.49 | length 1027.2
  L01-TOP w5.38: U1.49@1777.18,2162.87 1907.87,2162.87 v1(1980,2235)
  L01-TOP w7.27: v1(2052.75,1598.51) 2054.23,1600 R21.1@2086.3,1600
  L04-SIG w4.97: v1(1980,2235) 2030.33,2184.67 2030.33,2044.67 2102.32,1972.68 2102.32,1778.28 2102.32,1760.83 cw(c2094.83,1760.83) 2094.83,1753.34 2087.46,1753.34 ccw(c2087.46,1745.86) 2087.46,1738.37 2096.47,1738.37 cw(c2096.47,1730.89) 2096.47,1723.4 2094.63,1723.4 ccw(c2094.63,1715.91) 2094.63,1708.43 2094.83,1708.43 cw(c2094.83,1700.94) 2102.32,1700.94 2102.32,1657.73 2102.32,1648.09 v1(2052.75,1598.51)
P6_RGMII_TXD0: R22.1 U1.55 | length 1027.2
  L01-TOP w5.38: U1.55@1777.18,2257.36 1864.19,2257.36 v1(1880,2241.56)
  L01-TOP w7.27: v1(2047.87,1676.07) 2050.23,1676.07 2061.3,1665 R22.1@2086.3,1665
  L04-SIG w4.97: v1(1880,2241.56) 1912.9,2208.66 1912.9,1862.1 1965,1810 1979.22,1810 1982.73,1810 ccw(c1982.74,1822.78) 1991.76,1813.73 2008.06,1830.03 cw(c2013.35,1824.73) 2018.64,1830.03 cw(c2013.35,1824.73) 2018.64,1819.44 2002.68,1803.48 ccw(c2007.97,1798.19) 2002.68,1792.89 ccw(c2007.97,1798.19) 2013.27,1792.89 2025.33,1804.95 cw(c2030.62,1799.66) 2035.91,1804.96 cw(c2030.62,1799.66) 2035.91,1794.37 2023.85,1782.31 ccw(c2029.15,1777.02) 2023.85,1771.72 ccw(c2029.15,1777.02) 2034.44,1771.72 2064.58,1801.86 cw(c2069.87,1796.57) 2075.17,1801.86 cw(c2069.87,1796.57) 2075.17,1791.28 2054.74,1770.85 ccw(c2060.03,1765.56) 2054.74,1760.26 2070,1745 2070,1735.18 2070,1698.2 v1(2047.87,1676.07)
P6_RGMII_TXD1: R23.1 U1.54 | length 1027.2
  L01-TOP w5.38: U1.54@1777.21,2241.64 v1@1850.6,2241.64
  L01-TOP w7.27: v1(2051.24,1730.23) 2071.48,1710 R23.1@2086.3,1710
  L04-SIG w4.97: v1(1850.63,2241.67) 1900,2192.31 1900,1918.11 1900,1875.35 cw(c1892.51,1875.35) 1897.81,1870.06 1857.91,1830.16 ccw(c1863.21,1824.87) 1857.91,1819.58 ccw(c1863.21,1824.87) 1868.5,1819.58 1899.62,1850.7 cw(c1904.91,1845.4) 1910.2,1850.7 cw(c1904.91,1845.4) 1910.2,1840.11 1879.08,1808.99 ccw(c1884.38,1803.7) 1879.08,1798.4 ccw(c1884.38,1803.7) 1889.67,1798.4 1920.79,1829.52 cw(c1926.08,1824.23) 1931.38,1829.52 cw(c1926.08,1824.23) 1931.38,1818.94 1904.8,1792.36 ccw(c1910.1,1787.07) 1904.8,1781.78 ccw(c1910.1,1787.07) 1915.39,1781.78 1934.26,1800.65 cw(c1939.55,1795.35) 1944.84,1800.65 1955.87,1789.62 1965.99,1789.62 1991.85,1789.62 v1(2051.24,1730.23)
P6_RGMII_TXD2: R24.1 U1.53 | length 1027.8
  L01-TOP w5.38: U1.53@1777.18,2225.87 1890.87,2225.87 v1(1905,2240)
  L01-TOP w7.27: v1(2044.13,1818.64) 2045.8,1816.97 2048.34,1816.97 2085.31,1780 R24.1@2086.3,1780
  L04-SIG w4.97: v1(1905,2240) 1927.5,2217.5 1927.5,2177.25 1965.88,2138.88 1965.88,2134.52 1965.88,2122.06 cw(c1960.89,2122.06) 1960.89,2117.08 1953.09,2117.08 ccw(c1953.09,2112.09) 1953.09,2107.11 1961.56,2107.11 cw(c1961.56,2102.12) 1961.56,2097.13 1927.85,2097.13 ccw(c1927.85,2092.15) 1927.85,2087.16 1960.89,2087.16 cw(c1960.89,2082.18) 1960.89,2077.19 1927.85,2077.19 ccw(c1927.85,2072.21) 1927.85,2067.22 1960.89,2067.22 cw(c1960.89,2062.24) 1965.88,2062.24 1965.88,2022.35 cw(c1960.89,2022.35) 1960.89,2017.37 1927.85,2017.37 ccw(c1927.85,2012.38) 1927.85,2007.4 1963.76,2007.4 cw(c1963.76,2002.41) 1963.76,1997.42 1927.85,1997.42 ccw(c1927.85,1992.44) 1927.85,1987.45 1960.89,1987.45 cw(c1960.89,1982.47) 1965.88,1982.47 1965.88,1952.56 ccw(c1970.86,1952.56) 1970.86,1947.57 1971.71,1947.57 cw(c1971.71,1942.58) 1971.71,1937.6 1970.86,1937.6 ccw(c1970.86,1932.61) 1965.88,1932.61 1965.88,1924.96 1965.88,1896.89 v1(2044.13,1818.64)
P6_RGMII_TXD3: R25.1 U1.52 | length 1027.2
  L01-TOP w5.38: U1.52@1777.21,2210.15 1819.34,2210.15 1837.41,2210.15 cw(c1837.41,2202.46) 1845.1,2202.46 1845.1,2180.94 ccw(c1852.79,2180.94) 1860.48,2180.94 1860.48,2207.8 cw(c1868.16,2207.8) 1875.85,2207.8 1875.85,2180.94 ccw(c1883.54,2180.94) 1891.23,2180.94 1891.23,2202.46 cw(c1898.92,2202.46) 1898.92,2210.15 1920.15,2210.15 1927.83,2217.83 1934.06,2224.06 1934.06,2229.06 v1(1950,2245)
  L01-TOP w7.27: R25.1@2086.3,1825 2086.3,1857.82 v1(2086.83,1858.35)
  L04-SIG w4.97: v1(1950,2245) 1950,2243.1 2007.92,2185.18 2008.81,2184.29 2008.81,2175.98 ccw(c2013.8,2175.98) 2013.8,2171 2014.44,2171 cw(c2014.44,2166.01) 2014.44,2161.03 2013.8,2161.03 ccw(c2013.8,2156.04) 2013.8,2151.05 2015.37,2151.05 cw(c2015.37,2146.07) 2015.37,2141.08 2013.75,2141.08 ccw(c2013.75,2136.1) 2013.75,2131.11 2015.37,2131.11 cw(c2015.37,2126.13) 2015.37,2121.14 2012.71,2121.14 ccw(c2012.71,2116.16) 2012.71,2111.17 2015.37,2111.17 cw(c2015.37,2106.18) 2015.37,2101.2 2013.8,2101.2 ccw(c2013.8,2096.21) 2013.8,2091.23 2015.37,2091.23 cw(c2015.37,2086.24) 2015.37,2081.26 2013.8,2081.26 ccw(c2013.8,2076.27) 2008.81,2076.27 2008.81,2063.81 2008.81,2046.19 2081.22,1973.78 2086.83,1968.17 2086.83,1962.27 cw(c2079.35,1962.27) 2079.35,1954.79 2055.59,1954.79 ccw(c2055.59,1947.3) 2055.59,1939.82 2084.86,1939.82 cw(c2084.86,1932.33) 2084.86,1924.85 2068.07,1924.85 ccw(c2068.07,1917.36) 2068.07,1909.87 2084.86,1909.87 cw(c2084.86,1902.39) 2084.86,1894.9 2073.47,1894.9 ccw(c2073.47,1887.42) 2073.47,1879.93 2079.35,1879.93 cw(c2079.35,1872.45) 2086.83,1872.45 2086.83,1869.96 v1(2086.83,1858.35)
PCIe_CLK_N: J14.12 R118.1 | length 126.5
  L01-TOP w5.38: R118.1@2814.76,2245 cw(c2814.76,2242.62) 2816.44,2244.3 2825.18,2235.56 ccw(c2831.22,2241.6) 2831.22,2233.07 ccw(c2831.22,2271.98) 2858.73,2244.46 2880.26,2265.99 cw(c2906.78,2239.48) 2906.78,2276.98 ccw(c2906.78,2281.56) 2910.02,2278.32 cw(c2913.26,2275.08) 2913.26,2279.66 J14.12@2921.2,2279.66
PCIe_CLK_P: J14.10 R117.1 | length 126.3
  L01-TOP w5.38: R117.1@2814.78,2211.21 ccw(c2814.78,2213.59) 2816.46,2211.91 2824.43,2219.88 cw(c2831.22,2213.09) 2831.22,2222.69 ccw(c2831.22,2271.98) 2866.07,2237.12 2887.6,2258.65 cw(c2906.78,2239.48) 2906.78,2266.6 cw(c2906.78,2262.01) 2910.02,2265.26 ccw(c2913.26,2268.5) 2913.26,2263.91 J14.10@2921.2,2263.91
PCIE_CLK_R_N: R118.2 U18.22 | length 2865.9
  L01-TOP w5.38: v1(880,2400) ccw(c873.06,2400) 877.97,2404.91 877.34,2405.53 cw(c883.76,2411.94) 874.69,2411.94 874.69,2438.61 cw(c887.73,2438.61) 878.51,2447.83 ccw(c850.31,2476.03) 890.19,2476.03 890.19,2513.99 cw(c894.77,2513.99) 891.53,2517.23 ccw(c888.29,2520.47) 892.87,2520.47 U18.22@892.87,2525.16 ; v1(2755,2238.61) cw(c2755,2231.67) 2759.91,2236.57 2760.53,2235.95 ccw(c2766.95,2242.36) 2766.95,2233.29 2770.2,2233.29 ccw(c2770.2,2242.35) 2776.6,2235.94 ccw(c2775.4,2237.14) 2777.1,2237.14 cw(c2778.79,2237.14) 2777.6,2238.34 2783.56,2244.3 cw(c2785.24,2242.62) R118.2@2785.24,2245
  L06-BOT w5.38: v1(880,2400) ccw(c873.06,2400) 877.97,2404.91 877.34,2405.53 cw(c883.76,2411.94) 874.69,2411.94 874.69,2478.91 cw(c936.78,2478.91) 892.87,2522.82 cw(c911.68,2504.01) 911.68,2530.61 1074.27,2530.61 ccw(c1074.27,2579.72) 1109,2544.99 1122.17,2558.16 ccw(c1050.08,2630.24) 1152.02,2630.24 1152.02,2647.27 cw(c1219.68,2647.27) 1171.84,2695.11 1231.34,2754.61 cw(c1302.05,2683.9) 1302.05,2783.9 1850.1,2783.9 cw(c1850.1,2711.16) 1901.53,2762.59 ccw(c1944.91,2805.98) 1944.91,2744.62 2237.78,2744.62 ccw(c2237.78,2855) 2315.83,2776.95 2348.33,2809.46 cw(c2410,2747.79) 2410,2835 2468.58,2835 cw(c2468.58,2735) 2539.29,2805.71 2795.71,2549.29 cw(c2725,2478.58) 2825,2478.58 2825,2305.36 cw(c2739.64,2305.36) 2800,2245 cw(c2771.74,2273.26) 2773.64,2233.34 2773.5,2233.34 cw(c2773.5,2238.72) 2771.97,2233.56 v1(2755,2238.61)
PCIE_CLK_R_P: R117.2 U18.21 | length 2915.1
  L01-TOP w5.38: v1(859,2400) cw(c865.94,2400) 861.03,2404.91 861.66,2405.53 ccw(c855.24,2411.94) 864.31,2411.94 864.31,2438.61 cw(c887.73,2438.61) 871.17,2455.17 ccw(c850.31,2476.03) 879.81,2476.03 879.81,2513.99 ccw(c875.23,2513.99) 878.47,2517.23 cw(c881.71,2520.47) 877.13,2520.47 U18.21@877.13,2525.16 ; v1(2755,2217.61) ccw(c2755,2224.55) 2759.91,2219.64 2760.53,2220.26 cw(c2766.93,2213.85) 2766.93,2222.91 2770.21,2222.91 cw(c2770.21,2213.84) 2776.62,2220.26 cw(c2775.43,2219.06) 2777.12,2219.06 ccw(c2778.8,2219.06) 2777.61,2217.87 2783.58,2211.91 ccw(c2785.26,2213.59) R117.2@2785.26,2211.21
  L06-BOT w5.38: v1(859,2400) cw(c865.94,2400) 861.03,2404.91 861.66,2405.53 ccw(c855.24,2411.94) 864.31,2411.94 864.31,2478.91 cw(c936.78,2478.91) 885.54,2530.15 cw(c911.68,2504.01) 911.68,2540.98 1074.27,2540.98 ccw(c1074.27,2579.72) 1101.66,2552.33 1114.83,2565.5 ccw(c1050.08,2630.24) 1141.65,2630.24 1141.65,2647.27 cw(c1219.68,2647.27) 1164.5,2702.45 1224,2761.95 cw(c1302.05,2683.9) 1302.05,2794.27 1850.1,2794.27 cw(c1850.1,2711.16) 1908.87,2769.93 ccw(c1944.91,2805.98) 1944.91,2755 2237.78,2755 ccw(c2237.78,2855) 2308.49,2784.29 2340.99,2816.8 cw(c2410,2747.79) 2410,2845.38 2468.58,2845.38 cw(c2468.58,2735) 2546.63,2813.05 2803.05,2556.63 cw(c2725,2478.58) 2835.38,2478.58 2835.38,2305.36 cw(c2739.64,2305.36) 2807.34,2237.66 cw(c2771.74,2273.26) 2771.74,2222.92 2767.82,2222.92 v1(2755,2217.61)
PCIE_CLK_REQ_N: J14.2 R52.1 | length 85.8
  L01-TOP w6: J14.2@2921.2,2200.92 2921.24,2200.96 v1(2964,2201) v1(2964,2201)
  L06-BOT w7.27: v1(2964,2201) 2966.36,2201 2975.36,2210 R52.1@3003.27,2210
PCIE_PERST_N: J14.9 R119.1 U18.13 | length 3423.9
  L01-TOP w7.27: v1(690,2515) 690,2550 713.39,2573.39 U18.13@750.16,2573.39 ; J14.9@3042.46,2263.91 3068.91,2263.91 3080,2275 3163.9,2275 v1(3163.94,2275.04)
  L04-SIG w4.97: v1(690,2515) 688.33,2513.33 678.33,2513.33 658.36,2493.37 658.36,2444.74 673.59,2429.51 712.61,2429.51 727.88,2444.78 788.18,2444.78 808.15,2424.81 808.15,2386.05 834.2,2360 v1(882.81,2360)
  L06-BOT w7.27: v1(882.81,2360) 953.65,2360 1022.01,2428.37 1212.71,2428.37 1246.37,2462.02 1246.37,2540.4 1367.92,2661.94 1615.12,2661.94 1628.69,2648.37 1779.89,2648.37 1783.36,2651.83 2267.1,2651.83 2314.25,2604.69 2314.25,2504.27 2435.16,2383.37 2468.1,2383.37 2683.45,2168.01 2786.35,2168.01 2892.7,2274.37 3163.27,2274.37 v1(3163.94,2275.04) 3163.94,2276.23 3195,2307.28 R119.1@3195,2308.27
PCIe_RX_N: C184.1 J14.18 | length 129.9
  L01-TOP w5.38: C184.1@2799.39,2330 cw(c2799.39,2326.72) 2801.71,2329.04 2807.52,2323.23 cw(c2806.01,2321.72) 2808.14,2321.72 ccw(c2810.27,2321.72) 2808.77,2320.21 2809.72,2319.26 ccw(c2813.52,2323.07) 2813.52,2317.69 2834.99,2317.69 ccw(c2834.99,2319.48) 2836.26,2318.21 cw(c2850.76,2303.71) 2850.76,2324.22 2906.78,2324.22 ccw(c2906.78,2328.8) 2910.02,2325.56 cw(c2913.26,2322.32) 2913.26,2326.91 J14.18@2921.2,2326.91
PCIe_RX_P: C32.1 J14.16 | length 129.9
  L01-TOP w5.38: C32.1@2799.39,2295 ccw(c2799.39,2298.28) 2801.71,2295.96 2807.52,2301.77 ccw(c2806.01,2303.28) 2808.14,2303.28 cw(c2810.27,2303.28) 2808.77,2304.79 2809.72,2305.74 cw(c2813.52,2301.93) 2813.52,2307.31 2834.99,2307.31 ccw(c2834.99,2319.48) 2843.59,2310.87 cw(c2850.76,2303.71) 2850.76,2313.84 2906.78,2313.84 cw(c2906.78,2309.26) 2910.02,2312.5 ccw(c2913.26,2315.74) 2913.26,2311.16 J14.16@2921.2,2311.16
PCIe_TX_N: J14.24 R116.1 | length 139
  L01-TOP w5.38: R116.1@2799.76,2420 cw(c2799.76,2417.62) 2801.44,2419.3 2809.77,2410.98 ccw(c2817.73,2418.94) 2817.73,2407.68 cw(c2817.73,2375.94) 2840.18,2398.38 2857.97,2380.59 ccw(c2880,2402.62) 2880,2371.46 2906.78,2371.46 ccw(c2906.78,2376.05) 2910.02,2372.81 cw(c2913.26,2369.57) 2913.26,2374.15 J14.24@2921.2,2374.15
PCIe_TX_P: J14.22 R115.1 | length 139
  L01-TOP w5.38: R115.1@2799.76,2385 ccw(c2799.76,2387.38) 2801.44,2385.7 2809.74,2393.99 cw(c2817.73,2386) 2817.73,2397.3 cw(c2817.73,2375.94) 2832.84,2391.04 2850.63,2373.25 ccw(c2880,2402.62) 2880,2361.09 2906.78,2361.09 cw(c2906.78,2356.5) 2910.02,2359.74 ccw(c2913.26,2362.99) 2913.26,2358.4 J14.22@2921.2,2358.4
PHY_25MHz: C175.2 U4.46 | length 80.4
  L01-TOP w7.27: U4.46@2423.9,1621.14 2423.9,1585.14 2434.25,1574.79 C175.2@2434.25,1545
PHY_AVDDH: C101.1 C102.2 C103.1 C104.1 C105.1 FB7.2 U4.1 U4.12 | length 3085.8
  L01-TOP w5.38: U4.1@2488.86,1646.73 2490.49,1648.37 2513.37,1648.37 v1(2515,1650) ; U4.12@2488.86,1863.27 2511.3,1863.27 v1(2517.36,1869.33)
  L03-SIG w15: v1(2517.36,1869.33) 2470,1821.97 2470,1695 v1(2515,1650) 2515.19,1650.19 2544.88,1650.19 2552.05,1657.36 2552.05,1662.52 2570.98,1681.45 2622.4,1681.45 2709.46,1768.5 2709.46,1809.66 2818.05,1918.25 3318.32,1918.25 3640,1596.57 3640,645 3765.49,519.51 3765.49,420.49 3740,395 v1(3740,340)
  L06-BOT w15: v1(2515,1650) C104.1@2540.61,1650 ; v1(2517.36,1869.33) 2517.63,1869.33 2518.3,1870 C105.1@2545.61,1870
  other v1: 3765,355
PHY_AVDDL: C93.1 C94.2 C95.1 C96.1 C97.1 FB6.2 U4.4 U4.9 | length 1061.6
  L01-TOP w5.38: U4.4@2488.86,1705.79 2516.94,1705.79 v1(2517.12,1705.96) ; U4.9@2488.86,1804.21 2518.38,1804.21 v1(2518.59,1804.01)
  L03-SIG w15: v1(2450,2425) 2540,2425 2670,2295 2670,1919.68 2608.38,1858.06 2572.64,1858.06 v1(2518.59,1804.01) 2518.59,1707.7 2517.12,1706.23 v1(2517.12,1705.96)
  L06-BOT w15: v1(2517.12,1705.96) 2517.39,1705.96 2518.35,1705 C97.1@2545.61,1705 ; v1(2518.59,1804.01) 2518.86,1804.01 2519.85,1805 C96.1@2545.61,1805
  other v1: 2450,2450
PHY_AVDDL_PLL: C66.1 C67.2 C68.1 C69.1 FB5.2 U4.44 | length 1184.8
  L01-TOP w5.38: U4.44@2384.53,1621.14 2384.53,1600.47 v1(2409.31,1575.69)
  L03-SIG w15: v1(2409.31,1575.69) 2409.47,1575.53 2577.04,1575.53 2579.65,1572.92 2746.94,1572.92 2845.69,1671.67 2845.69,1764.24 2922.86,1841.41 3246.41,1841.41 v1(3275,1870) v1(3275,1895)
  L06-BOT w15: C69.1@2385,1625.61 2385,1624.25 2409.12,1600.13 2409.12,1575.88 v1(2409.31,1575.69)
PHY_DVDDH: C73.1 C74.2 C75.1 C76.1 C77.1 C182.1 R91.2 U4.16 U4.34 U4.40 | length 1679.6
  L01-TOP w5.38: v1(2194.87,1686.7) 2195.16,1686.4 2220.84,1686.4 U4.34@2221.14,1686.1 ; U4.40@2305.79,1621.14 2305.87,1621.06 2305.87,1597.94 v1(2305.95,1597.86) ; U4.16@2404.21,1888.86 2404.21,1919.55 v1(2404.73,1920.07)
  L03-SIG w15: v1(2305.95,1597.86) 2306.14,1597.67 2306.14,1591.37 2306.84,1590.67 2306.84,1572.82 2330,1549.66 ; v1(2404.73,1920.07) 2404.73,1954.46 2373.44,1985.75 2241.07,1985.75 2131.36,1876.03 2131.36,1750.21 v1(2194.87,1686.7) 2170,1661.83 2170,1594.53 2211.74,1552.8 2326.83,1552.8 2330,1549.62 2344.86,1534.76 2475.24,1534.76 2780.35,1229.66
  L06-BOT w15: v1(2194.87,1686.7) 2195.06,1686.5 2224.1,1686.5 C77.1@2225.61,1685 ; 2312.42,1604.61 2312.42,1628.03 C182.1@2315,1630.61 ; v1(2404.73,1920.07) 2404.86,1919.93 2404.86,1884.53 C76.1@2405,1884.39
  other v1: 3735,475 3735,495
PHY_DVDDL: C81.1 C82.2 C83.1 C84.1 C85.1 C86.1 C87.1 C88.1 C89.1 R92.2 U4.14 U4.18 U4.23 U4.26 U4.30 U4.39 | length 1199.4
  L01-TOP w5.38: v1(2196.13,1763.43) 2197.54,1764.84 U4.30@2221.14,1764.84 ; v1(2196.87,1843.83) 2197.12,1843.58 U4.26@2221.14,1843.58 ; v1(2265.87,1914.3) 2266.42,1913.75 U4.23@2266.42,1888.86 ; U4.39@2286.1,1621.14 2286.22,1621.02 2286.22,1582.29 v1(2286.34,1582.18) ; U4.18@2364.84,1888.86 2364.84,1913.89 v1(2365.38,1914.43) ; v1(2443.33,1914.43) 2443.58,1914.18 U4.14@2443.58,1888.86
  L03-SIG w15: v1(2286.34,1582.18) 2286.34,1582.45 2280.5,1588.29 2280.5,1679.07 v1(2196.13,1763.43) 2196.13,1763.71 2213.42,1780.99 2213.42,1827.01 2196.87,1843.56 v1(2196.87,1843.83) 2197.06,1844.03 2197.06,1845.5 v1(2265.87,1914.3) 2265.99,1914.43 v1(2365.38,1914.43) 2365.65,1914.43 2380.52,1899.57 2428.2,1899.57 2443.06,1914.43 v1(2443.33,1914.43) 2589.81,2060.91 2589.81,2079.81 v1(2590,2080)
  L06-BOT w15: C85.1@2195.65,1814.88 2195.65,1842.35 2196.87,1843.56 v1(2196.87,1843.83) ; v1(2196.13,1763.43) 2196.32,1763.24 2196.32,1738.62 2198.9,1736.04 C84.1@2199.82,1736.04 ; C89.1@2260,1615.61 2260,1614.25 2286.15,1588.11 2286.15,1582.37 v1(2286.34,1582.18) ; v1(2265.87,1914.3) 2266.14,1914.3 2268.4,1916.57 C86.1@2295.64,1916.57 ; C87.1@2360,1884.39 2362.58,1886.97 2362.58,1911.35 2365.38,1914.16 v1(2365.38,1914.43) ; v1(2443.33,1914.43) 2443.52,1914.62 2458.87,1914.62 2474.25,1930 C88.1@2475.61,1930
  other v1: 2615,2080
PHY_INT_N: J15.47 R87.2 | length 138
  L01-TOP w6: v1(4309,2566) 4313.87,2566 4318.87,2571 4342.48,2571 4350.35,2563.13 J15.47@4377.9,2563.13
  L06-BOT w6: v1(4309,2566) 4311.71,2566 4320.64,2574.94 R87.2@4369.05,2574.94
PHY_MDC: J15.54 R84.1 | length 148.8
  L01-TOP w7.27: v1(4184,2606) 4214.24,2606 4218.61,2610.37 J15.54@4256.64,2610.37
  L06-BOT w6: R84.1@4123.7,2640 4150,2640 v1(4184,2606)
PHY_MDIO: J15.50 R86.1 | length 142.5
  L01-TOP w6: v1(4209,2586) 4213.87,2586 4221,2578.87 J15.50@4256.64,2578.87
  L06-BOT w6: R86.1@4118.7,2590 4122.7,2586 v1(4209,2586)
PHY_RST_N: R81.1 R83.2 | length 44.6
  L01-TOP w7.27: R83.2@505,2563.7 R81.1@505,2608.27
SD_CLK: J15.57 SD1.5 | length 1840.4
  L01-TOP w6: v1(4334,2646.12) 4337.31,2642.8 4376.96,2642.8 J15.57@4377.9,2641.87
  L01-TOP w7.27: SD1.5@4221.85,970.47 v1(4295,970.47)
  L03-SIG w4.97: v1(4295,970.47) 4345,1020.47 4345,1038.62 4345,1277.8 4370,1302.8 4370,2610.12 v1(4334,2646.12)
SD_CMD: J15.62 SD1.3 | length 1848.4
  L01-TOP w6: v1(4210,2672.13) v1@4210.54,2672.13 ; v1@4210.55,2672.14 4230.86,2672.38 4234.49,2672.43 4255.7,2672.43 J15.62@4256.64,2673.36 ; SD1.3@4221.85,1057.09 4221.85,1057.35 v1(4302.35,1057.35)
  L03-SIG w4.97: v1(4210,2672.13) 4234.49,2647.64 4234.49,2218.25 4152.96,2136.72 4152.96,1206.74 v1(4302.35,1057.35)
SD_DAT0: J15.63 SD1.7 | length 2000.7
  L01-TOP w6: v1(4345,2690) 4345.44,2689.56 4377.45,2689.56 J15.63@4377.9,2689.11
  L01-TOP w7.27: SD1.7@4221.85,883.86 4305,883.86 v1(4305,885)
  L03-SIG w4.97: v1(4305,885) 4391.61,971.61 4391.61,1093.39 4365,1120 4365,1175 4392.68,1202.68 4392.68,2642.32 v1(4345,2690)
SD_DAT1: J15.67 SD1.8 | length 2226.5
  L01-TOP w6: v1(4309.42,2726) 4311.33,2724.09 4326.04,2724.09 4329.52,2720.61 J15.67@4377.9,2720.61
  L01-TOP w7.27: SD1.8@4221.85,840.55 4221.85,840 v1(4310,840)
  L03-SIG w4.97: v1(4309.42,2726) 4325,2710.42 4325,2662.42 4267.44,2604.86 4267.44,2177.72 4210,2120.28 4210,1290 4327.94,1172.06 4327.94,1047.94 4316.75,1036.75 4280.91,1036.75 4250,1005.85 4250,900 v1(4310,840)
SD_DAT2: J15.69 SD1.1 | length 1859.6
  L01-TOP w6: SD1.1@4221.85,1143.7 4223.15,1145 v1(4385,1145) ; v1(4334,2746) 4338.87,2746 4348.52,2736.35 J15.69@4377.9,2736.35
  L03-SIG w4.97: v1(4334,2746) 4416.24,2663.76 4416.24,1176.24 v1(4385,1145)
SD_DAT3: J15.61 SD1.2 | length 1839.4
  L01-TOP w6: SD1.2@4221.85,1100.39 4310,1100.39 v1(4310,1100) ; v1(4305.42,2670) 4308.12,2670 4311.49,2673.36 J15.61@4377.9,2673.36
  L03-SIG w4.97: v1(4305.42,2670) 4303.42,2670 4254.43,2621.01 4254.43,2204.86 4180,2130.43 4180,1230 v1(4310,1100)
SD_PWR: C15.1 SD1.4 U3.1 | length 669.8
  L01-TOP w20: C15.1@4123.64,710 4131.63,701.99 U3.1@4203.93,701.99 4203.93,733.28 4215.64,745 4340,745 4360,765 4360,885.67 4351.36,894.31 4351.36,1015 ; SD1.4@4221.85,1013.78 4300.63,1013.78 4300.63,1015.97
  L01-TOP w30: 4300.63,1015.97 4301.6,1015 4351.36,1015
